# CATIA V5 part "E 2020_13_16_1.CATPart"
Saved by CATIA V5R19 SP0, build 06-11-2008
Definition: E 2020_13_16_1
Nomenclature: E 2020_13_16_1
Description: PART--DESC
Material "Brass": density 8216 kg/m3, Young's modulus 1.31e+11 Pa, Poisson ratio 0.35, thermal expansion 1.67e-05 1/K
Bounding box of the stored display mesh (mm): x -9.815 to 9.815, y -8.5 to 8.5, z -12 to 18
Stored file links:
  G:\UTB\Kombinované\Bakalářská práce\Catia\FORMA\E 2020_13_16_1.CATPart
  D:\Aplikace\CATIA\Nová složka\win_b64\startup\materials\Catalog.CATMaterial
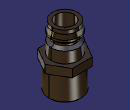
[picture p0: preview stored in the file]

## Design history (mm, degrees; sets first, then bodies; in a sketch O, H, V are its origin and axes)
Body1 "E 2020_13_16" (main body)
  Solid1: solid without history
